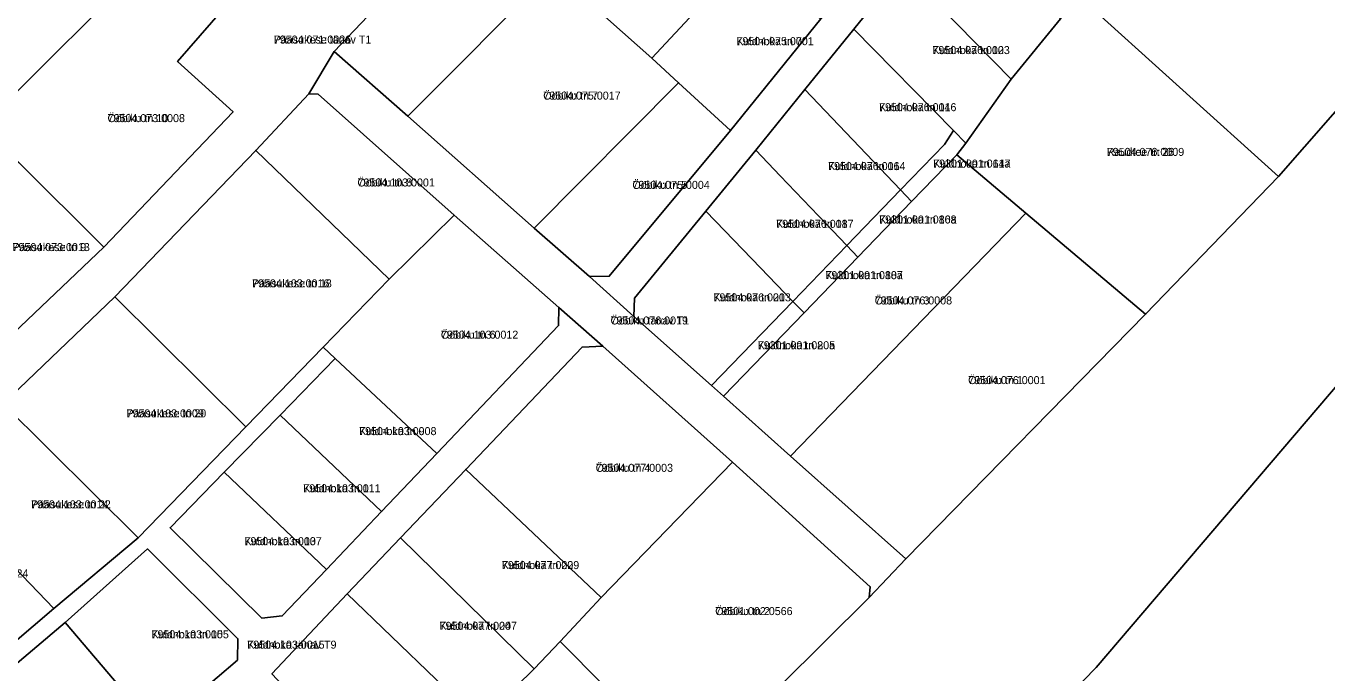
# Model space of a CAD drawing. Extents: x 643847 to 663718, y 6468443 to 6482775.
# Drawn here: x 658477 to 658720.9, y 6471569.9 to 6471691.2 of the extents above; entities that cross this region are included whole.
import ezdxf

# ---------------------------------------------------------------- set-up
doc = ezdxf.new("R2010")
doc.units = 0
for name, color, linetype in [('L_AADRESS', 7, 'Continuous'), ('PIIR', 7, 'Continuous'), ('TUNNUS', 7, 'Continuous')]:
    doc.layers.add(name, color=color, linetype=linetype)

msp = doc.modelspace()

# ---------------------------------------------------------------- linework, layer by layer
at = {"layer": 'PIIR'}
for points in [[(658586.66, 6471477.59), (658677.6, 6471570.91), (658723.5, 6471624.75), (658759, 6471670.33), (658782.07, 6471704.27), (658811.02, 6471742.52), (658820.56, 6471756.1), (658837, 6471780.62), (658853.3, 6471806.54), (658868.31, 6471832), (658875.45, 6471844.67), (658889.91, 6471871.15)], [(658601.72, 6471551.03), (658635.01, 6471584.07), (658641.89, 6471591.28), (658686.86, 6471637.14), (658711.75, 6471662.94), (658737.02, 6471691.74), (658761.55, 6471720.91), (658784.22, 6471751.11), (658811.02, 6471742.52), (658782.07, 6471704.27), (658759, 6471670.33), (658723.5, 6471624.75), (658677.6, 6471570.91), (658586.66, 6471477.59)], [(658542.27, 6471694.33), (658534.73, 6471686.38), (658529.96, 6471678.45), (658520.02, 6471667.86), (658493.61, 6471640.39), (658472.67, 6471620.33)], [(658473.31, 6471632.32), (658491.53, 6471649.71), (658515.77, 6471675.09), (658505.39, 6471684.51), (658513.89, 6471694.24)], [(658466.61, 6471568.78), (658482.16, 6471581.98), (658497.99, 6471595.25), (658518.19, 6471616.05), (658532.65, 6471630.95), (658534.93, 6471628.82), (658524.61, 6471618.26), (658514.13, 6471607.53), (658503.98, 6471597.13), (658521.18, 6471580.19), (658525, 6471580.61), (658533.28, 6471589.3), (658543.62, 6471600.16), (658553.96, 6471611.02), (658576.81, 6471635.01), (658576.83, 6471638.43), (658585.09, 6471631.14), (658581.22, 6471630.98), (658559.39, 6471608.05), (658547.15, 6471595.26), (658537.19, 6471584.73), (658528.04, 6471575.04), (658523.07, 6471569.78)], [(658501.38, 6471559.34), (658516.6, 6471572.33), (658516.68, 6471576.32), (658499.76, 6471593.15), (658484.28, 6471579.39), (658472.87, 6471569.66)]]:
    msp.add_lwpolyline(points, dxfattribs=at)
for points in [[(658690.05, 6471799.46), (658695.34, 6471796.83), (658680.73, 6471769.49), (658672.14, 6471753.43), (658664.97, 6471740.02), (658657.81, 6471726.6), (658651, 6471713.88), (658650.51, 6471713.27), (658641.32, 6471701.92), (658632.13, 6471690.58), (658622.94, 6471679.24), (658613.75, 6471667.9), (658604.38, 6471656.48), (658591.01, 6471640.18), (658590.93, 6471636.75), (658582.58, 6471644.21), (658586.3, 6471644.26), (658609.03, 6471671.6), (658625.98, 6471692.5), (658629.82, 6471697.3), (658647.74, 6471719.69), (658656.66, 6471736.46), (658669.1, 6471759.86), (658678.2, 6471777.17)], [(658501.73, 6471705.25), (658468.72, 6471672.48), (658460.74, 6471680.44), (658445.15, 6471696), (658444.67, 6471696.48), (658475.37, 6471728.35)], [(658711.75, 6471662.94), (658674.63, 6471696.49), (658693, 6471725.38), (658737.02, 6471691.74)], [(658534.73, 6471686.38), (658542.27, 6471694.33), (658532.79, 6471702.54), (658551.08, 6471723.59), (658565.24, 6471710.99), (658575.76, 6471701.61), (658548.56, 6471674.28)], [(658607.87, 6471707.34), (658611.88, 6471704.06), (658594.29, 6471685.13), (658580.55, 6471697.37), (658596.4, 6471716.74)], [(658650.51, 6471713.27), (658670.89, 6471692.53), (658661.66, 6471681.22), (658641.32, 6471701.92)], [(658475.55, 6471665.64), (658468.72, 6471672.48), (658501.73, 6471705.25), (658513.89, 6471694.24), (658505.39, 6471684.51), (658515.77, 6471675.09), (658491.53, 6471649.71)], [(658609.03, 6471671.6), (658599.3, 6471680.52), (658594.29, 6471685.13), (658611.88, 6471704.06), (658625.98, 6471692.5)], [(658548.56, 6471674.28), (658575.76, 6471701.61), (658580.55, 6471697.37), (658594.29, 6471685.13), (658599.3, 6471680.52), (658572.25, 6471653.28)], [(658641.32, 6471701.92), (658661.66, 6471681.22), (658653.14, 6471669.2), (658650.83, 6471671.55), (658632.13, 6471690.58)], [(658686.86, 6471637.14), (658664.42, 6471656.07), (658651.44, 6471667.04), (658653.14, 6471669.2), (658661.66, 6471681.22), (658670.89, 6471692.53), (658674.63, 6471696.49), (658711.75, 6471662.94)], [(658632.13, 6471690.58), (658650.83, 6471671.55), (658649.15, 6471668.98), (658640.91, 6471660.45), (658622.94, 6471679.24)], [(658641.89, 6471591.28), (658635.01, 6471584.07), (658635.24, 6471586.06), (658609.41, 6471609.42), (658585.09, 6471631.14), (658576.83, 6471638.43), (658557.2, 6471655.7), (658531.73, 6471678.38), (658529.96, 6471678.45), (658534.73, 6471686.38), (658548.56, 6471674.28), (658572.25, 6471653.28), (658582.58, 6471644.21), (658590.93, 6471636.75), (658605.47, 6471623.76), (658607.73, 6471621.8), (658620.31, 6471610.57)], [(658557.2, 6471655.7), (658545.06, 6471643.73), (658520.02, 6471667.86), (658529.96, 6471678.45), (658531.73, 6471678.38)], [(658572.25, 6471653.28), (658599.3, 6471680.52), (658609.03, 6471671.6), (658586.3, 6471644.26), (658582.58, 6471644.21)], [(658622.94, 6471679.24), (658640.91, 6471660.45), (658630.82, 6471650.01), (658625.52, 6471655.56), (658618.33, 6471663.1), (658613.75, 6471667.9)], [(658640.91, 6471660.45), (658649.15, 6471668.98), (658650.83, 6471671.55), (658653.14, 6471669.2), (658651.44, 6471667.04), (658642.99, 6471658.3)], [(658493.61, 6471640.39), (658520.02, 6471667.86), (658545.06, 6471643.73), (658532.65, 6471630.95), (658518.19, 6471616.05)], [(658604.38, 6471656.48), (658613.75, 6471667.9), (658618.33, 6471663.1), (658625.52, 6471655.56), (658630.82, 6471650.01), (658620.74, 6471639.56), (658614.65, 6471645.86), (658607.95, 6471652.79)], [(658607.73, 6471621.8), (658622.82, 6471637.42), (658632.92, 6471647.87), (658642.99, 6471658.3), (658651.44, 6471667.04), (658664.42, 6471656.07), (658620.31, 6471610.57)], [(658473.31, 6471632.32), (658457.48, 6471648.42), (658475.55, 6471665.64), (658491.53, 6471649.71)], [(658642.99, 6471658.3), (658632.92, 6471647.87), (658630.82, 6471650.01), (658640.91, 6471660.45)], [(658576.83, 6471638.43), (658576.81, 6471635.01), (658553.96, 6471611.02), (658534.93, 6471628.82), (658532.65, 6471630.95), (658545.06, 6471643.73), (658557.2, 6471655.7)], [(658591.01, 6471640.18), (658604.38, 6471656.48), (658607.95, 6471652.79), (658614.65, 6471645.86), (658620.74, 6471639.56), (658605.47, 6471623.76), (658590.93, 6471636.75)], [(658620.31, 6471610.57), (658664.42, 6471656.07), (658686.86, 6471637.14), (658641.89, 6471591.28)], [(658632.92, 6471647.87), (658622.82, 6471637.42), (658620.74, 6471639.56), (658630.82, 6471650.01)], [(658493.61, 6471640.39), (658518.19, 6471616.05), (658497.99, 6471595.25), (658472.67, 6471620.33)], [(658620.74, 6471639.56), (658622.82, 6471637.42), (658607.73, 6471621.8), (658605.47, 6471623.76)], [(658585.09, 6471631.14), (658609.41, 6471609.42), (658584.8, 6471584.08), (658559.39, 6471608.05), (658581.22, 6471630.98)], [(658543.62, 6471600.16), (658524.61, 6471618.26), (658534.93, 6471628.82), (658553.96, 6471611.02)], [(658482.16, 6471581.98), (658461.43, 6471603.54), (658457.82, 6471607.3), (658472.67, 6471620.33), (658497.99, 6471595.25)], [(658533.28, 6471589.3), (658514.13, 6471607.53), (658524.61, 6471618.26), (658543.62, 6471600.16)], [(658547.15, 6471595.26), (658559.39, 6471608.05), (658584.8, 6471584.08), (658577.09, 6471575.8), (658572.24, 6471570.71)], [(658584.8, 6471584.08), (658609.41, 6471609.42), (658635.24, 6471586.06), (658635.01, 6471584.07), (658601.72, 6471551.03), (658577.09, 6471575.8)], [(658457.82, 6471607.3), (658461.43, 6471603.54), (658482.16, 6471581.98), (658466.61, 6471568.78), (658442.78, 6471594.12)], [(658525, 6471580.61), (658521.18, 6471580.19), (658503.98, 6471597.13), (658514.13, 6471607.53), (658533.28, 6471589.3)], [(658516.6, 6471572.33), (658501.38, 6471559.34), (658484.28, 6471579.39), (658499.76, 6471593.15), (658516.68, 6471576.32)], [(658547.15, 6471595.26), (658572.24, 6471570.71), (658562.13, 6471560.74), (658537.19, 6471584.73)], [(658528.04, 6471575.04), (658537.19, 6471584.73), (658562.13, 6471560.74), (658547.59, 6471545.82), (658546.31, 6471544.76), (658528.81, 6471563.6), (658523.07, 6471569.78)], [(658489.97, 6471549.61), (658472.87, 6471569.66), (658484.28, 6471579.39), (658501.38, 6471559.34)], [(658577.09, 6471575.8), (658601.72, 6471551.03), (658578.24, 6471527.63), (658568.04, 6471524.66), (658547.59, 6471545.82), (658562.13, 6471560.74), (658572.24, 6471570.71)]]:
    msp.add_lwpolyline(points, close=True, dxfattribs=at)

# ---------------------------------------------------------------- texts
at = {"layer": 'L_AADRESS'}
for s, p in [('Pääsukese tänav T1', (658523.41, 6471687.88)), ('Kuldnoka tn 7', (658610.13, 6471687.57)), ('Kuldnoka tn 12', (658646.89, 6471685.9)), ('Ööbiku tn 7', (658573.93, 6471677.37)), ('Kuldnoka tn 14', (658636.88, 6471675.2)), ('Ööbiku tn 10', (658492.25, 6471673.15)), ('Raudtee tn 26', (658679.58, 6471666.82)), ('Kuldnoka tn 16', (658627.33, 6471664.16)), ('Kuldnoka tn 14a', (658647.02, 6471664.63)), ('Ööbiku tn 8', (658539.1, 6471661.09)), ('Ööbiku tn 5', (658590.64, 6471660.64)), ('Kuldnoka tn 18', (658617.6, 6471653.34)), ('Kuldnoka tn 16a', (658636.91, 6471654.15)), ('Pääsukese tn 9', (658474.42, 6471648.98)), ('Kuldnoka tn 18a', (658626.83, 6471643.72)), ('Pääsukese tn 18', (658519.34, 6471642.19)), ('Kuldnoka tn 20', (658605.84, 6471639.56)), ('Ööbiku tn 3', (658636.07, 6471638.98)), ('Ööbiku tänav T1', (658586.55, 6471635.23)), ('Ööbiku tn 6', (658554.74, 6471632.56)), ('Kuldnoka tn 20a', (658614.14, 6471630.59)), ('Ööbiku tn 1', (658653.59, 6471624.05)), ('Pääsukese tn 20', (658495.8, 6471617.82)), ('Kuldnoka tn 9', (658539.41, 6471614.49)), ('Ööbiku tn 4', (658583.75, 6471607.61)), ('Kuldnoka tn 11', (658528.94, 6471603.78)), ('Pääsukese tn 22', (658477.91, 6471600.77)), ('Kuldnoka tn 13', (658517.9, 6471593.86)), ('Kuldnoka tn 22', (658566.17, 6471589.38)), ('Pääsukese tn 24', (658462.47, 6471587.82)), ('Ööbiku tn 2', (658606.17, 6471580.76)), ('Kuldnoka tn 24', (658554.49, 6471578)), ('Kuldnoka tn 15', (658500.48, 6471576.41)), ('Kuldnoka tänav T9', (658518.44, 6471574.47))]:
    msp.add_text(s, height=1.5, dxfattribs=at).set_placement(p)
at = {"layer": 'TUNNUS'}
for s, p in [('79504:071:0026', (658523.41, 6471687.88)), ('79504:075:0001', (658610.13, 6471687.57)), ('79504:076:0003', (658646.89, 6471685.9)), ('79504:075:0017', (658573.93, 6471677.37)), ('79504:076:0016', (658636.88, 6471675.2)), ('79504:073:0008', (658492.25, 6471673.15)), ('79504:076:0009', (658679.58, 6471666.82)), ('79504:076:0014', (658627.33, 6471664.16)), ('79301:001:0617', (658647.02, 6471664.63)), ('79504:103:0001', (658539.1, 6471661.09)), ('79504:075:0004', (658590.64, 6471660.64)), ('79504:076:0017', (658617.6, 6471653.34)), ('79301:001:0808', (658636.91, 6471654.15)), ('79504:073:0013', (658474.42, 6471648.98)), ('79301:001:0807', (658626.83, 6471643.72)), ('79504:103:0016', (658519.34, 6471642.19)), ('79504:076:0013', (658605.84, 6471639.56)), ('79504:076:0008', (658636.07, 6471638.98)), ('79504:076:0019', (658586.55, 6471635.23)), ('79504:103:0012', (658554.74, 6471632.56)), ('79301:001:0805', (658614.14, 6471630.59)), ('79504:076:0001', (658653.59, 6471624.05)), ('79504:103:0009', (658495.8, 6471617.82)), ('79504:103:0008', (658539.41, 6471614.49)), ('79504:077:0003', (658583.75, 6471607.61)), ('79504:103:0011', (658528.94, 6471603.78)), ('79504:103:0014', (658477.91, 6471600.77)), ('79504:103:0007', (658517.9, 6471593.86)), ('79504:077:0009', (658566.17, 6471589.38)), ('79501:002:0566', (658606.17, 6471580.76)), ('79504:077:0007', (658554.49, 6471578)), ('79504:103:0005', (658500.48, 6471576.41)), ('79504:103:0015', (658518.44, 6471574.47))]:
    msp.add_text(s, height=1.5, dxfattribs=at).set_placement(p)

doc.saveas('drawing.dxf')
